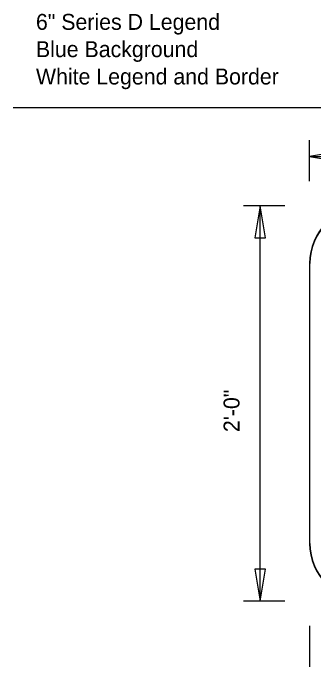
# Model space of a CAD drawing. Extents: x 0 to 770, y 0 to 495.
# Drawn here: x 0 to 66.1, y 207.1 to 350.7 of the extents above; entities that cross this region are included whole.
import ezdxf

# ---------------------------------------------------------------- set-up
doc = ezdxf.new("R2010")
doc.units = 0
for name, color, linetype in [('Dimension', 7, 'Continuous'), ('GSBWFill', 7, 'Continuous'), ('GSColorFill', 7, 'Continuous'), ('GSDims', 7, 'Continuous'), ('GSOutline', 7, 'Continuous'), ('SheetLines_dp', 7, 'Continuous'), ('TextStructures', 7, 'Continuous')]:
    doc.layers.add(name, color=color, linetype=linetype)

msp = doc.modelspace()

# ---------------------------------------------------------------- linework, layer by layer
at = {"layer": 'Dimension'}
for points in [[(65.11, 319.21), (72.12, 318.02), (72.12, 320.4)], [(54.26, 308.36), (53.07, 301.34), (55.45, 301.34)], [(54.26, 221.55), (55.45, 228.56), (53.07, 228.56)]]:
    msp.add_lwpolyline(points, close=True, dxfattribs=at)
at = {"layer": 'GSBWFill'}
msp.add_line((65.11, 295.7), (65.11, 234.21), dxfattribs=at)
for centre, start, end in [((77.77, 295.7), 90, 180), ((77.77, 234.21), 180, 270)]:
    msp.add_arc(centre, 12.66, start, end, dxfattribs=at)
at = {"layer": 'GSColorFill'}
for p, q in [((65.11, 295.7), (65.11, 234.21)), ((65.11, 295.7), (65.11, 234.21)), ((65.2, 234.21), (65.2, 295.7))]:
    msp.add_line(p, q, dxfattribs=at)
for centre, radius, start, end in [((77.77, 295.7), 12.66, 90, 180), ((77.77, 295.7), 12.66, 90, 180), ((77.77, 295.7), 12.57, 90, 180), ((77.77, 234.21), 12.66, 180, 270), ((77.77, 234.21), 12.66, 180, 270), ((77.77, 234.21), 12.57, 180, 270)]:
    msp.add_arc(centre, radius, start, end, dxfattribs=at)
at = {"layer": 'GSDims'}
for p, q in [((65.11, 313.78), (65.11, 322.83)), ((65.11, 319.21), (151.92, 319.21)), ((59.68, 308.36), (50.64, 308.36)), ((54.26, 221.55), (54.26, 308.36)), ((59.68, 221.55), (50.64, 221.55)), ((65.11, 216.12), (65.11, 207.08))]:
    msp.add_line(p, q, dxfattribs=at)
at = {"layer": 'GSOutline'}
msp.add_line((65.11, 295.7), (65.11, 234.21), dxfattribs=at)
for centre, start, end in [((77.77, 295.7), 90, 180), ((77.77, 234.21), 180, 270)]:
    msp.add_arc(centre, 12.66, start, end, dxfattribs=at)
at = {"layer": 'SheetLines_dp'}
msp.add_line((0, 330), (770, 330), dxfattribs=at)

# ---------------------------------------------------------------- texts
at = {"layer": 'TextStructures'}
for s, p in [('6" Series D Legend', (5.02, 347.03)), ('Blue Background', (5.02, 341.03)), ('White Legend and Border', (5.02, 335.03))]:
    msp.add_text(s, height=3.5, dxfattribs=at).set_placement(p)
msp.add_text('2\'-0"', height=3.5, rotation=90, dxfattribs=at).set_placement((49.73, 258.67))

doc.saveas('drawing.dxf')
